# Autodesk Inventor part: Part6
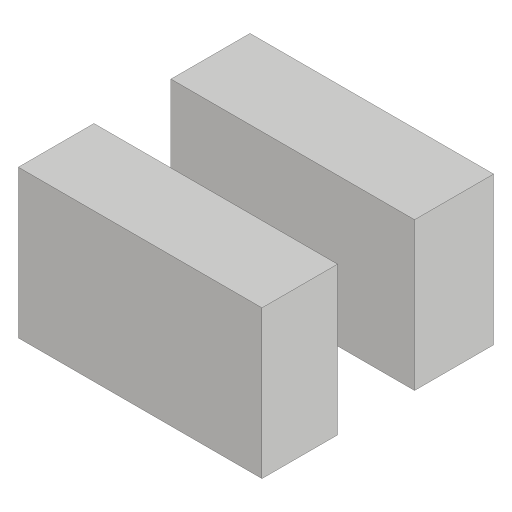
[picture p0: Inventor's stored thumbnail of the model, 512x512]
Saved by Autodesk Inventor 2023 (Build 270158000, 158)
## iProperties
Created: 2015-07
Part Number: Part6
Material: Generic
Document SubType Name: Modeling
Designer: Sandeep
Density: 1 g/cm^3
Appearance: Default
Author: Sandeep
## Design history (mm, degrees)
sketch "Sketch1"
  geometry: L1 (-17.042, 14.133)-(12.609, 14.133); L2 (12.609, 14.133)-(12.609, -14.063); L3 (12.609, -14.063)-(-17.042, -14.063); L4 (-17.042, -14.063)-(-17.042, 14.133); 1 further point
  constraints: 8 end point, 2 parallel, 1 horizontal, 1 perpendicular
extrude "Extrusion1" new body sketch "Sketch1" distance "d0" = 18; taper "d1" = 0 deg
sketch "Sketch2"
  geometry: L1 (-18, 28.196)-(-18, 0) reference; L2 (-18, 9.203)-(0.196, 9.203); L3 (0.196, 9.203)-(0.196, 18.574); L4 (0.196, 18.574)-(-18, 18.574); L5 (-18, 18.574)-(-18, 9.203); 1 further point
  constraints: 8 end point, 2 parallel, 1 horizontal, 1 perpendicular, 1 point on line
extrude "Extrusion2" cut sketch "Sketch2" distance "d2" = 8; taper "d3" = 0 deg
node "Direct Edit1"
body "Solid1"
feature "Delete1"
